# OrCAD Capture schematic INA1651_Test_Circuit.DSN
size A; title: INA1651 SoundPlus High Common-Mode Rejection Line Receivers; rev: 1.2; note: Datasheet: SBOS818B  EVM: SBOU212
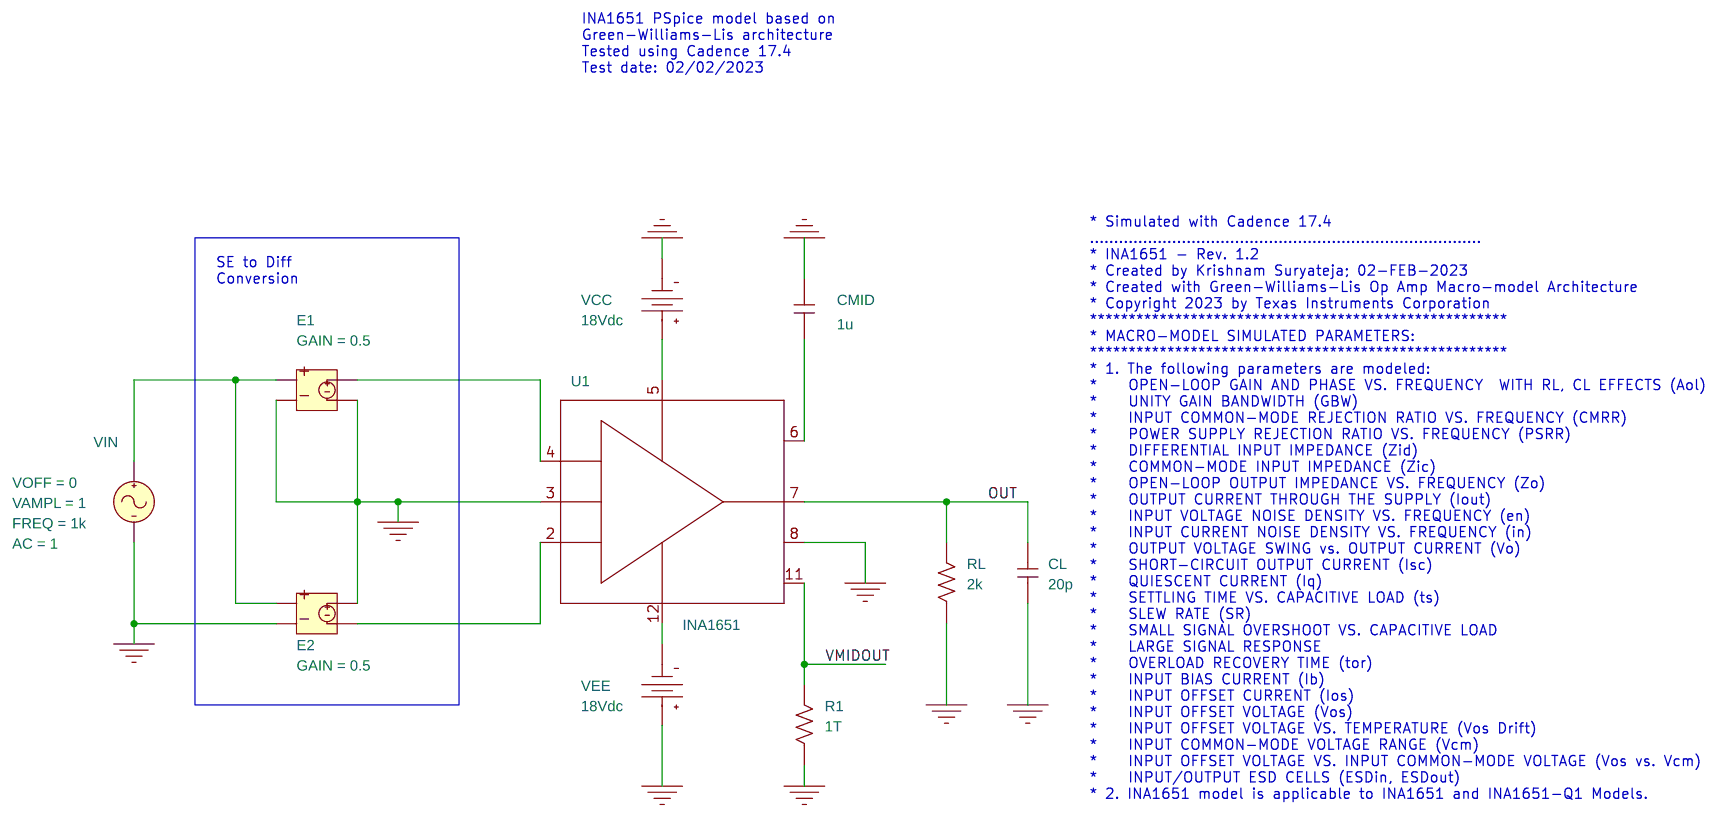
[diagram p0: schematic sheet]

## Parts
CL  20p  [RAD/CK05]
CMID  1u  [RAD/CK05]
E1  E
E2  E
R1  1T  [AX/RC05]
RL  2k  [AX/RC05]
U1  INA1651
VCC  VDC
VEE  VDC
VIN  VSIN

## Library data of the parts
CL CMID = C
E1 E2 = E: GAIN: 0.5
R1 RL = R
U1 = INA1651
VCC VEE = VDC: DC: 18Vdc
VIN = VSIN: AC: 1; FREQ: 1k; VAMPL: 1; VOFF: 0

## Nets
0: CL.1 CMID.1 E1.2 E1.4 E2.2 E2.3 R1.1 RL.1 U1.3(COM) U1.8(REF) VCC.1(-) VEE.0(+) VIN.2(-)
OUT: CL.2 RL.2 U1.7(OUT)
VMIDOUT: R1.2 U1.11(VMIDOUT)
N00578: U1.5(V+) VCC.0(+)
N00742: E1.1 E2.1 VIN.1(+)
N00923: E2.4 U1.2(-)
N01149: E1.3 U1.4(+)
N29179: U1.12(V-) VEE.1(-)
N33821: CMID.2 U1.6(VMIDIN)

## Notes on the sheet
- INA1651 PSpice model based on
  Green-Williams-Lis architecture
  Tested using Cadence 17.4
  Test date: 02/02/2023
- * Simulated with Cadence 17.4
  .................................................................................
  * INA1651 - Rev. 1.2
  * Created by Krishnam Suryateja; 02-FEB-2023
  * Created with Green-Williams-Lis Op Amp Macro-model Architecture
  * Copyright 2023 by Texas Instruments Corporation
  ******************************************************
  * MACRO-MODEL SIMULATED PARAMETERS:
  ******************************************************
  * 1. The following parameters are modeled:
  *    OPEN-LOOP GAIN AND PHASE VS. FREQUENCY  WITH RL, CL EFFECTS (Aol)
  *    UNITY GAIN BANDWIDTH (GBW)
  *    INPUT COMMON-MODE REJECTION RATIO VS. FREQUENCY (CMRR)
  *    POWER SUPPLY REJECTION RATIO VS. FREQUENCY (PSRR)
  *    DIFFERENTIAL INPUT IMPEDANCE (Zid)
  *    COMMON-MODE INPUT IMPEDANCE (Zic)
  *    OPEN-LOOP OUTPUT IMPEDANCE VS. FREQUENCY (Zo)
  *    OUTPUT CURRENT THROUGH THE SUPPLY (Iout)
  *    INPUT VOLTAGE NOISE DENSITY VS. FREQUENCY (en)
  *    INPUT CURRENT NOISE DENSITY VS. FREQUENCY (in)
  *    OUTPUT VOLTAGE SWING vs. OUTPUT CURRENT (Vo)
  *    SHORT-CIRCUIT OUTPUT CURRENT (Isc)
  *    QUIESCENT CURRENT (Iq)
  *    SETTLING TIME VS. CAPACITIVE LOAD (ts)
  *    SLEW RATE (SR)
  *    SMALL SIGNAL OVERSHOOT VS. CAPACITIVE LOAD
  *    LARGE SIGNAL RESPONSE
  *    OVERLOAD RECOVERY TIME (tor)
  *    INPUT BIAS CURRENT (Ib)
  *    INPUT OFFSET CURRENT (Ios)
  *    INPUT OFFSET VOLTAGE (Vos)
  *    INPUT OFFSET VOLTAGE VS. TEMPERATURE (Vos Drift)
  *    INPUT COMMON-MODE VOLTAGE RANGE (Vcm)
  *    INPUT OFFSET VOLTAGE VS. INPUT COMMON-MODE VOLTAGE (Vos vs. Vcm)
  *    INPUT/OUTPUT ESD CELLS (ESDin, ESDout)
  * 2. INA1651 model is applicable to INA1651 and INA1651-Q1 Models.
- SE to Diff
  Conversion
